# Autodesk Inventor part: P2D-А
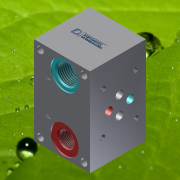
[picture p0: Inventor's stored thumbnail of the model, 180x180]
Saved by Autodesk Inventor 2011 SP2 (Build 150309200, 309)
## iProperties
Created: 2013-11
Part Number: P2D-А
Document SubType Name: Modeling
Designer: dorohin
Density: 1 g/cm^3
Author: dorohin
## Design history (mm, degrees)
derived "1560122-06.ipt"
feature "Solid1::1560122-06.ipt" dims "d0" = 10
tag "Элемент создания маркировки1"
node "Твердое тело1"
